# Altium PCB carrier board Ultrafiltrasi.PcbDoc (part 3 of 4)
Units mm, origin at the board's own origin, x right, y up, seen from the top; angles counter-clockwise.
Board outline 196.34 x 220.85 mm, 2 copper layers (Top Layer, Bottom Layer); 114 components, 209 nets, 667 pads, 70 vias.
Unrouted connection lines stored in the file: 5.
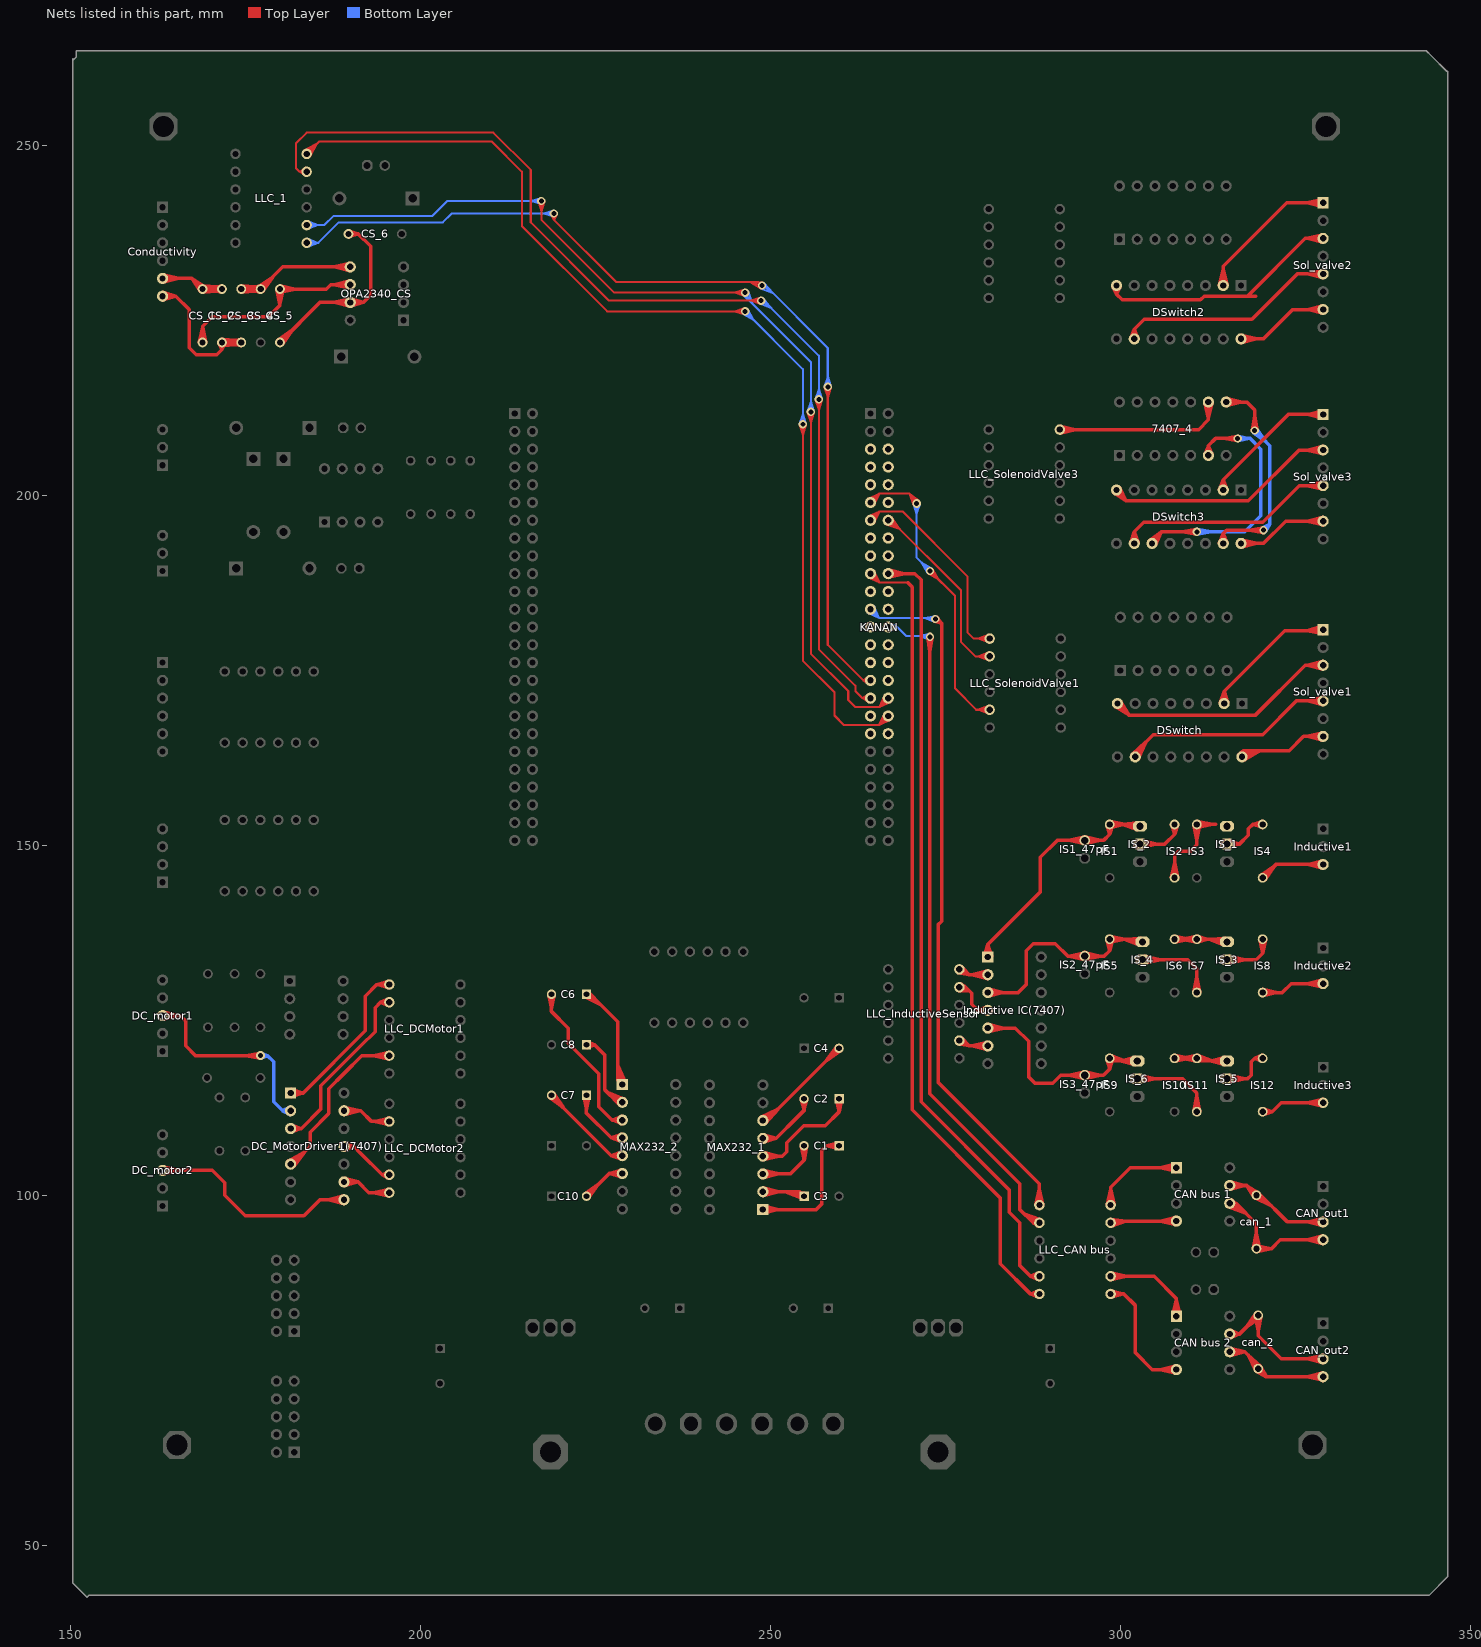
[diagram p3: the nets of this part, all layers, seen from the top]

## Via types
v1: diameter 1.2, hole 0.711, Top Layer to Bottom Layer, 26 vias
v2: diameter 1.27, hole 0.711, Top Layer to Bottom Layer, 24 vias
v3: diameter 1.2, hole 0.7, Top Layer to Bottom Layer, 19 vias
v4: diameter 1.5, hole 0.8, Top Layer to Bottom Layer, 1 vias

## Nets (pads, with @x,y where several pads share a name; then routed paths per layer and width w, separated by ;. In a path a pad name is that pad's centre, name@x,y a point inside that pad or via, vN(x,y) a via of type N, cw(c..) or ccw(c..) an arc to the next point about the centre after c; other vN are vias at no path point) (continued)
Net7407_4_6: 7407_4.6 DSwitch3.11 | length 64.6
  Top Layer w0.5: DSwitch3.11@304.124,193.562 305.816,194.818 ; DSwitch3.11@304.979,192.884 305.816,194.818 ; v3@310.867,194.469 308.796,194.818 v3@310.867,195.167 ; v3@311.162,195.072 311.15,195.072 v3(310.896,194.818) 305.816,194.818 ; 7407_4.6@312.008,205.848 312.547,207.137 ; 7407_4.6@312.547,205.74 312.547,207.137 ; 7407_4.6@313.086,205.848 312.547,207.137 ; v1@316.709,207.804 314.638,208.153 ; v1@316.709,208.502 314.638,208.153 ; 305.816,194.818 DSwitch3.11@304.507,193.167 304.507,193.509 305.816,194.818 ; 312.547,207.137 313.563,208.153 v1(316.738,208.153) 314.638,208.153
  Bottom Layer w0.5: v3(310.896,194.818) 317.754,194.818 320.04,197.104 320.04,206.629 318.516,208.153 ; v3@310.925,194.469 312.996,194.818 v3@310.925,195.167 ; v1(316.738,208.153) 318.516,208.153 ; v1@316.772,207.805 318.516,208.153 ; v1@316.772,208.501 318.516,208.153
Net7407_4_8: 7407_4.8 DSwitch3.15 | length 55.5
  Top Layer w0.5: DSwitch3.15@314.127,193.272 314.667,194.603 ; DSwitch3.15@314.667,193.167 314.667,194.603 ; 7407_4.8@315.087,213.36 318.008,213.36 319.151,212.217 v3(319.151,209.296) ; 7407_4.8@315.153,212.814 317.387,213.36 7407_4.8@315.153,213.906 ; DSwitch3.15@315.207,193.272 314.667,194.603 ; v3@318.802,209.325 319.151,211.396 v3@319.5,209.325 ; v3@320.392,194.723 318.321,195.072 ; v3@320.392,195.421 318.321,195.072 ; 314.667,194.603 315.136,195.072 v3(320.421,195.072) 318.321,195.072
  Bottom Layer w0.5: v3@318.923,209.031 320.812,207.635 v3@319.416,209.524 ; v3(319.151,209.296) 321.31,207.137 321.31,195.961 ; v3@320.21,195.352 321.31,195.961 ; v3(320.421,195.072) 321.31,195.961 ; v3@320.701,194.861 321.31,195.961
Net7407_4_9: 7407_4.9 LLC_SolenoidValve3.P$12 | length 33.4
  Top Layer w0.5: LLC_SolenoidValve3.P$12@291.338,209.423 311.15,209.423 312.547,210.82 7407_4.9@312.547,213.36 ; LLC_SolenoidValve3.P$12@291.394,208.926 293.588,209.423 LLC_SolenoidValve3.P$12@291.394,209.92 ; 7407_4.9@312.001,213.294 312.547,211.06 7407_4.9@313.093,213.294
NetC1_1: C1.1 MAX232_1.1 | length 27.3
  Top Layer w0.5: MAX232_1.1@248.92,98.044 256.54,98.044 257.302,98.806 257.302,106.426 258.032,107.156 ; MAX232_1.1@248.986,97.498 251.22,98.044 MAX232_1.1@248.986,98.59 ; C1.1@259.751,106.734 258.032,107.156 ; C1.1@259.751,107.578 258.032,107.156 ; C1.1@259.802,107.156 258.032,107.156
NetC1_2: C1.2 MAX232_1.3 | length 19.6
  Top Layer w0.5: MAX232_1.3@248.92,103.124 252.857,103.124 254.802,105.069 ; MAX232_1.3@248.986,102.578 251.22,103.124 MAX232_1.3@248.986,103.67 ; C1.2@254.379,107.113 254.802,105.069 ; C1.2@255.225,107.113 254.802,105.069 ; 254.802,105.069 C1.2@254.802,107.156 254.802,105.069
NetC2_1: C2.1 MAX232_1.4 | length 26.6
  Top Layer w0.5: MAX232_1.4@248.92,105.664 251.714,105.664 252.349,106.299 252.349,107.569 254.762,109.982 257.81,109.982 259.802,111.974 ; MAX232_1.4@248.986,105.118 251.22,105.664 MAX232_1.4@248.986,106.21 ; C2.1@259.38,113.807 259.802,111.974 ; C2.1@259.802,113.855 259.802,111.974 ; C2.1@259.802,114.088 259.802,111.974 ; C2.1@260.224,113.807 259.802,111.974
NetC2_2: C2.2 MAX232_1.5 | length 18
  Top Layer w0.5: MAX232_1.5@248.92,108.204 250.825,108.204 ; MAX232_1.5@248.999,107.66 250.825,108.204 ; MAX232_1.5@248.999,108.748 250.825,108.204 ; C2.2@254.38,113.802 254.802,112.181 ; C2.2@255.224,113.802 254.802,112.181 ; 250.825,108.204 253.873,111.252 254.802,112.181 ; 254.802,112.181 C2.2@254.802,113.855 254.802,112.181
NetC3_1: C3.1 MAX232_1.2 | length 19.1
  Top Layer w0.5: MAX232_1.2@248.92,100.584 254.167,100.584 C3.1@254.802,99.949 252.103,100.584 ; MAX232_1.2@248.986,100.038 251.22,100.584 MAX232_1.2@248.986,101.13 ; C3.1@254.673,99.544 252.103,100.584 ; C3.1@254.867,100.369 252.103,100.584
NetC4_2: C4.2 MAX232_1.6 | length 30.6
  Top Layer w0.5: MAX232_1.6@248.633,111.213 251.066,112.382 ; MAX232_1.6@249.297,110.343 251.066,112.382 ; C4.2@259.481,121.341 258.04,119.356 ; C4.2@259.774,121.09 249.428,110.744 MAX232_1.6@248.92,110.744 251.066,112.382 ; C4.2@259.802,121.063 258.04,119.356 ; C4.2@260.07,120.733 258.04,119.356
NetC6_1: C6.1 MAX232_2.1 | length 31.3
  Top Layer w0.5: C6.1@223.513,128.415 225.771,127.289 ; C6.1@224.013,129.099 225.771,127.289 ; MAX232_2.1@228.309,115.821 228.219,118.628 ; MAX232_2.1@229.375,116.068 228.219,118.628 ; 225.771,127.289 C6.1@223.734,128.778 224.282,128.778 228.219,124.841 228.219,116.527 MAX232_2.1@228.854,115.892 228.219,118.628
NetC6_2: C6.2 MAX232_2.3 | length 31.8
  Top Layer w0.5: C6.2@218.311,128.736 218.734,126.603 C6.2@219.157,128.736 ; C6.2@218.734,128.778 218.734,126.325 221.107,123.952 221.107,121.793 225.464,117.436 225.464,112.737 227.389,110.812 ; MAX232_2.3@228.751,110.272 227.389,110.812 ; MAX232_2.3@228.751,111.352 227.389,110.812 ; 227.389,110.812 MAX232_2.3@228.854,110.812 227.389,110.812
NetC7_1: C7.1 MAX232_2.4 | length 20.4
  Top Layer w0.5: C7.1@223.311,114.322 223.734,112.189 ; C7.1@224.157,114.322 223.734,112.189 ; MAX232_2.4@228.759,107.73 227.262,108.272 ; MAX232_2.4@228.759,108.814 227.262,108.272 ; 223.734,112.189 C7.1@223.734,114.364 223.734,111.8 227.262,108.272 ; 227.262,108.272 MAX232_2.4@228.854,108.272 227.262,108.272
NetC7_2: C7.2 MAX232_2.5 | length 24.3
  Top Layer w0.5: C7.2@218.451,114.046 220.415,112.579 ; C7.2@218.63,114.364 227.262,105.732 ; C7.2@218.734,114.364 220.415,112.579 ; C7.2@219.067,114.627 220.415,112.579 ; MAX232_2.5@228.759,105.19 227.262,105.732 ; MAX232_2.5@228.759,106.274 227.262,105.732 ; MAX232_2.5@228.854,105.732 227.262,105.732
NetC8_1: C8.1 MAX232_2.2 | length 21.6
  Top Layer w0.5: C8.1@223.734,121.571 224.885,121.571 ; C8.1@223.812,121.153 224.885,121.571 ; C8.1@223.812,121.988 224.885,121.571 ; MAX232_2.2@228.5,112.931 226.676,114.827 ; MAX232_2.2@229.113,113.837 226.676,114.827 ; 224.885,121.571 226.314,120.142 226.314,115.189 228.151,113.352 MAX232_2.2@228.854,113.352 226.676,114.827
NetC10_2: C10.2 MAX232_2.6 | length 15.1
  Top Layer w0.5: C10.2@223.461,100.274 225.47,101.685 C10.2@224.059,99.676 ; C10.2@223.734,99.949 226.977,103.192 ; MAX232_2.6@228.773,102.648 226.977,103.192 ; MAX232_2.6@228.773,103.736 226.977,103.192 ; MAX232_2.6@228.854,103.192 226.977,103.192
"NetCAN bus 1_1": "CAN bus 1.1" "LLC_CAN bus.P$12" | length 22.2
  Top Layer w0.5: 298.08,98.735 298.577,100.929 299.074,98.735 ; 298.577,98.679 298.577,101.219 301.371,104.013 307.975,104.013 ; 307.909,103.467 305.675,104.013 307.909,104.559
"NetCAN bus 1_4": "CAN bus 1.4" "LLC_CAN bus.P$11" | length 23.4
  Top Layer w0.5: 298.576,96.639 300.879,96.393 ; 298.685,95.651 300.879,96.393 ; 307.909,95.847 305.675,96.393 ; 307.909,96.939 305.675,96.393 ; 300.879,96.393 298.577,96.139 298.831,96.393 307.975,96.393 305.675,96.393
"NetCAN bus 2_1": "CAN bus 2.1" "LLC_CAN bus.P$8" | length 22.4
  Top Layer w0.5: 298.577,88.519 304.8,88.519 307.975,85.344 307.975,82.804 ; 298.633,88.022 300.827,88.519 298.633,89.016 ; 307.429,82.87 307.975,85.104 308.521,82.87
"NetCAN bus 2_4": "CAN bus 2.4" "LLC_CAN bus.P$7" | length 26.2
  Top Layer w0.5: 298.577,85.979 300.482,85.979 ; 298.643,85.483 300.482,85.979 ; 298.643,86.475 300.482,85.979 ; 307.909,74.638 305.675,75.184 307.909,75.73 ; 307.975,75.184 304.546,75.184 302.133,77.597 302.133,84.328 300.482,85.979
Netcan_1_1: "CAN bus 1.6" can_1.1 CAN_out1.4 | length 44.5
  Top Layer w0.5: 315.357,98.437 317.889,97.528 ; 315.929,99.37 317.889,97.528 ; can_1.1@318.957,92.502 319.405,94.656 can_1.1@319.853,92.502 ; can_1.1@319.452,92.008 321.564,92.456 ; can_1.1@319.452,92.904 321.564,92.456 ; CAN_out1.4@328.864,93.18 326.63,93.726 CAN_out1.4@328.864,94.272 ; CAN_out1.4@328.93,93.726 322.834,93.726 321.564,92.456 ; 315.595,98.933 316.484,98.933 ; 315.595,98.933 317.889,97.528 ; 315.595,98.933 316.484,98.933 ; 316.484,98.933 315.765,98.41 316.484,98.933 ; 316.484,98.933 315.765,99.456 316.484,98.933 ; 316.484,98.933 319.405,96.012 can_1.1@319.405,92.456 321.564,92.456
Netcan_1_2: "CAN bus 1.7" can_1.2 CAN_out1.3 | length 36.4
  Top Layer w0.5: 315.595,101.473 318.008,101.473 ; 315.661,100.927 317.895,101.473 315.661,102.019 ; can_1.2@319.053,99.796 318.008,101.473 ; can_1.2@319.18,99.686 321.527,98.589 ; can_1.2@319.685,100.428 318.008,101.473 ; can_1.2@319.694,100.421 321.527,98.589 ; CAN_out1.3@328.864,95.72 326.63,96.266 CAN_out1.3@328.864,96.812 ; CAN_out1.3@328.93,96.266 323.85,96.266 320.04,100.076 can_1.2@319.405,100.076 ; 318.008,101.473 can_1.2@319.405,100.076 ; can_1.2@319.405,100.076 321.527,98.589
Netcan_2_1: "CAN bus 2.6" can_2.1 CAN_out2.4 | length 34.7
  Top Layer w0.5: 315.595,77.724 317.754,77.724 ; 315.665,77.178 317.754,77.724 ; 315.665,78.27 317.754,77.724 ; can_2.1@319.275,75.076 318.185,77.293 ; can_2.1@319.388,74.952 320.802,74.168 ; can_2.1@319.994,75.611 318.185,77.293 ; can_2.1@320.018,75.582 320.802,74.168 ; CAN_out2.4@328.864,73.622 326.63,74.168 CAN_out2.4@328.864,74.714 ; CAN_out2.4@328.93,74.168 320.802,74.168 ; 317.754,77.724 319.659,75.819 can_2.1@319.659,75.311 ; 318.185,77.293 can_2.1@319.659,75.311 ; can_2.1@319.659,75.311 320.802,74.168
Netcan_2_2: "CAN bus 2.7" can_2.2 CAN_out2.3 | length 35.5
  Top Layer w0.5: 315.595,80.264 316.992,80.264 ; 315.703,79.725 316.992,80.264 ; 315.703,80.803 316.992,80.264 ; can_2.2@319.211,82.885 319.659,80.731 can_2.2@320.107,82.885 ; can_2.2@319.313,83.219 317.898,81.17 can_2.2@319.947,82.585 ; CAN_out2.3@328.864,76.162 326.63,76.708 CAN_out2.3@328.864,77.254 ; CAN_out2.3@328.93,76.708 322.961,76.708 319.659,80.01 can_2.2@319.659,82.931 316.992,80.264
NetConductivity_5: Conductivity.5 CS_1.1 CS_2.2 | length 40.2
  Top Layer w0.5: Conductivity.5@163.195,231.013 167.386,231.013 ; Conductivity.5@163.261,230.467 165.495,231.013 Conductivity.5@163.261,231.559 ; CS_1.1@168.56,229.206 167.386,231.013 ; CS_1.1@168.886,229.04 CS_2.2@171.117,229.147 ; CS_1.1@168.886,229.938 CS_2.2@171.117,229.831 ; CS_1.1@168.956,229.041 171.11,229.489 CS_1.1@168.956,229.937 ; CS_1.1@169.023,229.054 CS_2.2@171.117,229.831 ; CS_1.1@169.023,229.924 CS_2.2@171.117,229.147 ; CS_1.1@169.193,229.839 167.386,231.013 ; CS_2.2@171.626,229.041 169.472,229.489 CS_2.2@171.626,229.937 ; CS_2.2@171.672,229.489 CS_1.1@168.91,229.489 ; 167.386,231.013 CS_1.1@168.91,229.489 ; CS_1.1@168.91,229.489 CS_2.2@171.117,229.831 ; CS_1.1@168.91,229.489 CS_2.2@171.117,229.147
NetConductivity_6: Conductivity.6 CS_2.1 CS_3.1 | length 47.4
  Top Layer w0.5: Conductivity.6@163.195,228.473 165.1,228.473 ; Conductivity.6@163.274,227.929 165.1,228.473 ; Conductivity.6@163.274,229.017 165.1,228.473 ; CS_2.1@171.233,221.772 171.672,220.821 ; CS_2.1@171.649,221.42 CS_3.1@173.879,221.527 ; CS_2.1@171.649,222.318 CS_3.1@173.879,222.211 ; CS_2.1@171.718,221.421 173.872,221.869 CS_2.1@171.718,222.317 ; CS_2.1@171.786,221.434 CS_3.1@173.879,222.211 ; CS_2.1@171.786,222.304 CS_3.1@173.879,221.527 ; CS_2.1@172.112,221.772 171.672,220.821 ; CS_3.1@174.388,221.421 172.235,221.869 CS_3.1@174.388,222.317 ; CS_3.1@174.434,221.869 CS_2.1@171.672,221.869 ; 165.1,228.473 167.005,226.568 167.005,221.107 168.021,220.091 170.942,220.091 171.672,220.821 ; 171.672,220.821 CS_2.1@171.672,221.869 ; CS_2.1@171.672,221.869 CS_3.1@173.879,221.527 ; CS_2.1@171.672,221.869 CS_3.1@173.879,222.211
NetCS_1_2: CS_1.2 CS_5.1 OPA2340_CS.6 | length 47.2
  Top Layer w0.5: CS_1.2@168.462,221.915 168.91,224.069 CS_1.2@169.358,221.915 ; CS_1.2@168.91,221.869 168.91,224.155 170.307,225.552 178.308,225.552 179.959,227.203 CS_5.1@179.959,229.489 ; CS_5.1@179.511,229.443 179.959,227.289 ; CS_5.1@180.005,229.041 182.159,229.489 CS_5.1@180.005,229.937 ; CS_5.1@180.407,229.443 179.959,227.289 ; OPA2340_CS.6@189.926,229.578 187.692,230.124 OPA2340_CS.6@189.926,230.67 ; OPA2340_CS.6@189.992,230.124 187.198,230.124 186.563,229.489 CS_5.1@179.959,229.489 ; 179.959,227.289 CS_5.1@179.959,229.489
NetCS_3_2: CS_3.2 CS_4.2 OPA2340_CS.5 | length 48.7
  Top Layer w0.5: CS_3.2@174.411,229.04 CS_4.2@176.641,229.147 ; CS_3.2@174.411,229.938 CS_4.2@176.641,229.831 ; CS_3.2@174.481,229.041 176.634,229.489 CS_3.2@174.481,229.937 ; CS_3.2@174.548,229.054 CS_4.2@176.641,229.831 ; CS_3.2@174.548,229.924 CS_4.2@176.641,229.147 ; CS_4.2@176.909,229.835 178.957,231.25 CS_4.2@177.542,229.201 ; CS_4.2@177.151,229.041 174.997,229.489 CS_4.2@177.151,229.937 ; OPA2340_CS.5@189.926,232.118 187.692,232.664 OPA2340_CS.5@189.926,233.21 ; OPA2340_CS.5@189.992,232.664 180.372,232.664 CS_4.2@177.197,229.489 CS_3.2@174.434,229.489 ; CS_3.2@174.434,229.489 CS_4.2@176.641,229.831 ; CS_3.2@174.434,229.489 CS_4.2@176.641,229.147
NetCS_5_2: CS_5.2 CS_6.1 OPA2340_CS.7 | length 42.8
  Top Layer w0.5: CS_5.2@179.671,222.215 181.72,223.63 CS_5.2@180.305,221.581 ; CS_5.2@179.959,221.869 185.674,227.584 OPA2340_CS.7@189.992,227.584 191.897,227.584 ; CS_6.1@189.738,237.363 191.135,237.363 ; CS_6.1@189.81,236.919 191.135,237.363 ; CS_6.1@189.81,237.807 191.135,237.363 ; OPA2340_CS.7@189.926,227.038 187.692,227.584 OPA2340_CS.7@189.926,228.13 ; OPA2340_CS.7@190.071,227.04 191.897,227.584 ; OPA2340_CS.7@190.071,228.128 191.897,227.584 ; 191.135,237.363 192.913,235.585 192.913,228.6 191.897,227.584
NetDC_motor1_3: DC_motor1.3 DC_MotorDriver1(7407).2 | length 44.7
  Top Layer w0.5: DC_motor1.3@163.195,125.73 165.735,125.73 166.497,124.968 166.497,121.412 167.894,120.015 v2(177.165,120.015) 175.03,120.015 ; DC_motor1.3@163.261,125.184 165.495,125.73 DC_motor1.3@163.261,126.276 ; v2@177.13,119.632 175.03,120.015 ; v2@177.13,120.398 175.03,120.015
  Bottom Layer w0.5: v2(177.165,120.015) 178.181,120.015 ; v2@177.238,119.637 178.181,120.015 ; v2@177.238,120.393 178.181,120.015 ; 181.351,111.607 180.34,112.141 ; 181.351,112.675 180.34,112.141 ; 181.483,112.141 180.34,112.141 ; 178.181,120.015 179.07,119.126 179.07,113.411 180.34,112.141
NetDC_motor2_3: DC_motor2.3 DC_MotorDriver1(7407).8 | length 39.8
  Top Layer w0.5: DC_motor2.3@163.195,103.632 170.307,103.632 172.085,101.854 172.085,100.076 175.006,97.155 183.388,97.155 185.674,99.441 189.103,99.441 ; DC_motor2.3@163.261,103.086 165.495,103.632 DC_motor2.3@163.261,104.178 ; 189.037,98.895 186.803,99.441 189.037,99.987
NetDC_MotorDriver1(7407)_1: DC_MotorDriver1(7407).1 LLC_DCMotor1.P$7 | length 32.3
  Top Layer w0.5: 181.483,114.681 183.261,114.681 ; 181.568,114.138 183.261,114.681 ; 181.568,115.224 183.261,114.681 ; LLC_DCMotor1.P$7@195.51,129.68 193.802,130.175 ; LLC_DCMotor1.P$7@195.51,130.67 193.802,130.175 ; 183.261,114.681 192.151,123.571 192.151,128.524 193.802,130.175 ; 193.802,130.175 LLC_DCMotor1.P$7@195.58,130.175 193.802,130.175
NetDC_MotorDriver1(7407)_3: DC_MotorDriver1(7407).3 LLC_DCMotor1.P$8 | length 32.4
  Top Layer w0.5: 181.483,109.601 183.007,109.601 ; 181.582,109.06 183.007,109.601 ; 181.582,110.142 183.007,109.601 ; LLC_DCMotor1.P$8@195.482,127.145 194.31,127.635 ; LLC_DCMotor1.P$8@195.482,128.125 194.31,127.635 ; 183.007,109.601 185.801,112.395 185.801,115.697 191.516,121.412 193.548,123.444 193.548,126.873 194.31,127.635 ; 194.31,127.635 LLC_DCMotor1.P$8@195.58,127.635 194.31,127.635
NetDC_MotorDriver1(7407)_5: DC_MotorDriver1(7407).5 LLC_DCMotor1.P$11 | length 36.1
  Top Layer w0.5: 181.168,104.972 183.441,106.225 ; 181.886,104.147 183.441,106.225 ; LLC_DCMotor1.P$11@195.524,119.518 193.33,120.015 LLC_DCMotor1.P$11@195.524,120.512 ; LLC_DCMotor1.P$11@195.58,120.015 191.643,120.015 189.103,117.475 186.944,115.316 186.944,111.76 184.277,109.093 184.277,107.061 181.737,104.521 181.483,104.521 183.441,106.225
NetDC_MotorDriver1(7407)_9: DC_MotorDriver1(7407).9 LLC_DCMotor2.P$12 | length 15.7
  Top Layer w0.5: 189.103,101.981 191.135,101.981 ; 189.177,101.436 191.135,101.981 ; 189.177,102.526 191.135,101.981 ; LLC_DCMotor2.P$12@195.524,99.96 193.33,100.457 LLC_DCMotor2.P$12@195.524,100.954 ; LLC_DCMotor2.P$12@195.58,100.457 192.659,100.457 191.135,101.981
NetDC_MotorDriver1(7407)_11: DC_MotorDriver1(7407).11 LLC_DCMotor2.P$11 | length 13
  Top Layer w0.5: 189.103,107.061 190.5,107.061 ; 189.211,106.522 190.5,107.061 ; 189.211,107.6 190.5,107.061 ; LLC_DCMotor2.P$11@195.457,102.512 194.564,102.997 ; LLC_DCMotor2.P$11@195.457,103.482 194.564,102.997 ; LLC_DCMotor2.P$11@195.58,102.997 194.564,102.997 ; 190.5,107.061 191.516,106.045 194.564,102.997
NetDC_MotorDriver1(7407)_13: DC_MotorDriver1(7407).13 LLC_DCMotor2.P$8 | length 16.2
  Top Layer w0.5: 189.103,112.141 191.516,112.141 193.04,110.617 LLC_DCMotor2.P$8@195.58,110.617 ; 189.169,111.595 191.403,112.141 189.169,112.687 ; LLC_DCMotor2.P$8@195.524,110.12 193.33,110.617 LLC_DCMotor2.P$8@195.524,111.114
NetDSwitch2_2: DSwitch2.2 Sol_valve2.1 | length 32.1
  Top Layer w0.5: DSwitch2.2@314.121,230.063 314.667,232.297 DSwitch2.2@315.213,230.063 ; DSwitch2.2@314.667,229.997 314.667,232.752 323.723,241.808 Sol_valve2.1@328.803,241.808 ; Sol_valve2.1@328.864,241.262 326.63,241.808 ; Sol_valve2.1@328.864,242.354 326.63,241.808 ; Sol_valve2.1@328.93,241.808 326.63,241.808
NetDSwitch2_8: DSwitch2.8 Sol_valve2.3 | length 45.1
  Top Layer w0.5: DSwitch2.8@298.891,229.874 299.427,228.766 ; DSwitch2.8@299.427,229.997 299.427,228.766 ; DSwitch2.8@299.963,229.874 299.427,228.766 ; 318.135,228.473 326.39,236.728 Sol_valve2.3@328.803,236.728 ; 319.278,228.473 311.942,228.473 311.419,227.95 300.243,227.95 299.427,228.766 ; Sol_valve2.3@328.864,236.182 326.63,236.728 ; Sol_valve2.3@328.864,237.274 326.63,236.728 ; Sol_valve2.3@328.93,236.728 326.63,236.728
NetDSwitch2_10: DSwitch2.10 Sol_valve2.5 | length 41
  Top Layer w0.5: DSwitch2.10@301.428,222.488 301.967,223.735 ; DSwitch2.10@301.967,222.377 301.967,223.735 ; DSwitch2.10@302.506,222.488 301.967,223.735 ; Sol_valve2.5@328.676,231.648 325.247,231.648 318.77,225.171 303.403,225.171 301.967,223.735 ; Sol_valve2.5@328.864,231.102 326.63,231.648 ; Sol_valve2.5@328.864,232.194 326.63,231.648 ; Sol_valve2.5@328.93,231.648 326.63,231.648
NetDSwitch2_16: DSwitch2.16 Sol_valve2.7 | length 22.7
  Top Layer w0.5: DSwitch2.16@317.207,222.377 320.421,222.377 324.612,226.568 Sol_valve2.7@328.93,226.568 ; DSwitch2.16@317.273,221.831 319.507,222.377 DSwitch2.16@317.273,222.923 ; Sol_valve2.7@328.864,226.022 326.63,226.568 Sol_valve2.7@328.864,227.114
NetDSwitch3_2: DSwitch3.2 Sol_valve3.1 | length 29.2
  Top Layer w0.5: DSwitch3.2@314.127,200.889 314.667,202.272 ; DSwitch3.2@314.667,200.787 314.667,202.272 ; DSwitch3.2@315.208,200.889 314.667,202.272 ; 323.977,211.582 314.667,202.272 ; 324.104,211.582 Sol_valve3.1@328.803,211.582 ; Sol_valve3.1@328.864,211.036 326.63,211.582 ; Sol_valve3.1@328.864,212.128 326.63,211.582 ; Sol_valve3.1@328.93,211.582 326.63,211.582
NetDSwitch3_8: DSwitch3.8 Sol_valve3.3 | length 45.9
  Top Layer w0.5: DSwitch3.8@299.063,200.375 300.736,199.263 ; DSwitch3.8@299.889,201.085 300.736,199.263 ; Sol_valve3.3@328.676,206.502 325.501,206.502 318.262,199.263 300.736,199.263 ; Sol_valve3.3@328.864,205.956 326.63,206.502 ; Sol_valve3.3@328.864,207.048 326.63,206.502 ; Sol_valve3.3@328.93,206.502 326.63,206.502 ; 300.736,199.263 DSwitch3.8@299.427,200.787 299.427,200.572 300.736,199.263
NetDSwitch3_10: DSwitch3.10 Sol_valve3.5 | length 41.4
  Top Layer w0.5: DSwitch3.10@301.424,193.256 301.967,194.857 ; DSwitch3.10@301.967,193.167 301.967,194.857 ; DSwitch3.10@302.51,193.256 301.967,194.857 ; Sol_valve3.5@328.676,201.422 325.501,201.422 320.294,196.215 303.325,196.215 301.967,194.857 ; Sol_valve3.5@328.864,200.876 326.63,201.422 ; Sol_valve3.5@328.864,201.968 326.63,201.422 ; Sol_valve3.5@328.93,201.422 326.63,201.422
NetDSwitch3_16: DSwitch3.16 Sol_valve3.7 | length 24.3
  Top Layer w0.5: DSwitch3.16@317.207,193.167 320.421,193.167 323.596,196.342 Sol_valve3.7@328.676,196.342 ; DSwitch3.16@317.273,192.621 319.507,193.167 DSwitch3.16@317.273,193.713 ; Sol_valve3.7@328.864,195.796 326.63,196.342 ; Sol_valve3.7@328.864,196.888 326.63,196.342 ; Sol_valve3.7@328.93,196.342 326.63,196.342
NetDSwitch_2: DSwitch.2 Sol_valve1.1 | length 29.9
  Top Layer w0.5: DSwitch.2@314.251,170.394 314.794,172.046 ; DSwitch.2@314.794,170.307 314.794,172.046 ; DSwitch.2@315.337,170.394 314.794,172.046 ; Sol_valve1.1@328.835,181.39 326.623,180.721 ; Sol_valve1.1@328.895,180.299 326.623,180.721 ; Sol_valve1.1@328.93,180.721 323.469,180.721 314.794,172.046 ; Sol_valve1.1@328.93,180.848 326.623,180.721
NetDSwitch_8: DSwitch.8 Sol_valve1.3 | length 42.3
  Top Layer w0.5: DSwitch.8@299.214,169.875 301.205,168.656 ; DSwitch.8@299.554,170.307 301.205,168.656 ; DSwitch.8@299.986,170.647 301.205,168.656 ; Sol_valve1.3@328.864,175.222 326.63,175.768 Sol_valve1.3@328.864,176.314 ; Sol_valve1.3@328.93,175.768 326.39,175.768 319.278,168.656 301.205,168.656
NetDSwitch_10: DSwitch.10 Sol_valve1.5 | length 50.7
  Top Layer w0.5: DSwitch.10@301.684,163.053 303.615,164.804 ; DSwitch.10@302.572,162.415 303.615,164.804 ; 324.993,170.561 320.294,165.862 304.673,165.862 302.387,163.576 ; 325.12,170.688 Sol_valve1.5@328.93,170.688 326.63,170.688 ; Sol_valve1.5@328.864,170.142 326.63,170.688 ; Sol_valve1.5@328.864,171.234 326.63,170.688 ; DSwitch.10@302.094,162.687 302.387,163.576 ; DSwitch.10@302.094,162.687 303.615,164.804 ; DSwitch.10@302.094,162.687 302.387,163.576 ; DSwitch.10@302.094,162.687 302.387,162.98 302.387,163.576 ; 302.387,163.576 302.644,162.676 302.387,163.576 ; 302.387,163.576 301.645,163.005 302.387,163.576
NetDSwitch_16: DSwitch.16 Sol_valve1.7 | length 32.6
  Top Layer w0.5: DSwitch.16@317.21,163.223 319.954,163.576 ; DSwitch.16@317.562,162.186 319.954,163.576 ; Sol_valve1.7@328.781,165.079 327.914,165.608 ; Sol_valve1.7@328.781,166.137 327.914,165.608 ; Sol_valve1.7@328.864,165.062 326.63,165.608 Sol_valve1.7@328.864,166.154 ; DSwitch.16@317.334,162.687 317.5,163.576 ; DSwitch.16@317.334,162.687 319.954,163.576 ; DSwitch.16@317.334,162.687 317.5,163.576 ; DSwitch.16@317.334,162.687 317.334,163.41 317.5,163.576 ; 317.5,163.576 317.88,162.755 317.5,163.576 ; 317.5,163.576 316.85,162.948 317.5,163.576 ; 317.5,163.576 324.104,163.576 326.136,165.608 327.914,165.608
NetInductive1_3: Inductive1.3 IS4.2 | length 19
  Top Layer w0.5: IS4.2@320.006,145.761 322.055,147.176 IS4.2@320.64,145.127 ; IS4.2@320.294,145.415 322.199,147.32 Inductive1.3@328.93,147.32 ; Inductive1.3@328.864,146.774 326.63,147.32 Inductive1.3@328.864,147.866
NetInductive2_3: Inductive2.3 IS8.2 | length 18.2
  Top Layer w0.5: IS8.2@320.294,129.032 323.088,129.032 324.358,130.302 Inductive2.3@328.93,130.302 ; IS8.2@320.34,128.584 322.494,129.032 IS8.2@320.34,129.48 ; Inductive2.3@328.864,129.756 326.63,130.302 Inductive2.3@328.864,130.848
NetInductive3_3: Inductive3.3 IS12.2 | length 16.5
  Top Layer w0.5: IS12.2@320.294,112.014 321.691,112.014 ; IS12.2@320.366,111.57 321.691,112.014 ; IS12.2@320.366,112.458 321.691,112.014 ; Inductive3.3@328.874,112.787 326.68,113.284 Inductive3.3@328.874,113.781 ; Inductive3.3@328.93,113.284 322.961,113.284 321.691,112.014
"NetInductive IC(7407)_1": "Inductive IC(7407).1" IS1.2 IS1_47pF.2 IS_2.1 | length 61.1
  Top Layer w0.5: 280.508,134.197 281.051,135.89 ; 281.051,134.112 281.051,135.89 ; 281.594,134.197 281.051,135.89 ; IS1_47pF.2@294.836,150.24 292.632,150.749 IS1_47pF.2@294.836,151.258 ; IS1_47pF.2@294.952,150.24 297.156,150.749 IS1_47pF.2@294.952,151.258 ; IS1.2@298.006,152.963 298.45,151.638 ; IS1.2@298.496,152.587 300.65,153.035 IS1.2@298.496,153.483 ; IS1.2@298.894,152.963 298.45,151.638 ; IS_2.1@302.401,152.282 300.228,153.035 ; IS_2.1@302.514,152.781 300.228,153.035 ; IS_2.1@302.514,153.293 300.228,153.035 ; IS_2.1@302.768,152.781 302.514,153.035 IS1.2@298.45,153.035 298.45,151.638 ; 281.051,135.89 288.544,143.383 288.544,148.336 290.957,150.749 IS1_47pF.2@294.894,150.749 297.561,150.749 298.45,151.638
"NetInductive IC(7407)_2": "Inductive IC(7407).2" LLC_InductiveSensor.P$12 | length 13.8
  Top Layer w0.5: LLC_InductiveSensor.P$12@276.82,131.863 278.384,131.572 ; LLC_InductiveSensor.P$12@276.987,132.334 278.384,131.572 ; LLC_InductiveSensor.P$12@276.987,132.461 277.495,132.461 278.384,131.572 ; LLC_InductiveSensor.P$12@277.292,132.73 278.384,131.572 ; 280.985,131.026 278.751,131.572 280.985,132.118 ; 281.051,131.572 278.384,131.572
"NetInductive IC(7407)_3": "Inductive IC(7407).3" IS2_47pF.2 IS5.2 IS_4.1 | length 61.4
  Top Layer w0.5: 281.051,129.032 285.369,129.032 286.512,130.175 286.512,135.001 287.528,136.017 290.703,136.017 292.481,134.239 IS2_47pF.2@294.894,134.239 ; 281.117,128.486 283.351,129.032 281.117,129.578 ; IS2_47pF.2@294.836,133.73 292.632,134.239 ; IS2_47pF.2@294.836,134.748 292.632,134.239 ; IS2_47pF.2@294.952,133.73 297.156,134.239 IS2_47pF.2@294.952,134.748 ; IS5.2@298.004,136.591 298.45,135.001 ; IS5.2@298.496,136.204 300.65,136.652 IS5.2@298.496,137.1 ; IS5.2@298.896,136.591 298.45,135.001 ; IS_4.1@302.758,135.778 300.566,136.652 ; IS_4.1@302.895,136.271 300.566,136.652 ; IS_4.1@302.922,136.782 300.566,136.652 ; IS_4.1@303.149,136.271 302.768,136.652 IS5.2@298.45,136.652 298.45,135.001 ; 292.632,134.239 IS2_47pF.2@294.894,134.239 ; IS2_47pF.2@294.894,134.239 297.688,134.239 298.45,135.001
"NetInductive IC(7407)_4": "Inductive IC(7407).4" LLC_InductiveSensor.P$11 | length 18.3
  Top Layer w0.5: LLC_InductiveSensor.P$11@276.898,129.302 278.384,129.286 ; LLC_InductiveSensor.P$11@276.987,129.921 277.749,129.921 ; LLC_InductiveSensor.P$11@277.234,130.228 278.384,129.286 ; 280.943,125.953 279.654,126.492 ; 280.943,127.031 279.654,126.492 ; 281.051,126.492 279.654,126.492 ; LLC_InductiveSensor.P$11@276.987,129.794 277.749,129.921 ; LLC_InductiveSensor.P$11@276.987,129.794 278.384,129.286 ; LLC_InductiveSensor.P$11@276.987,129.794 277.749,129.921 ; 277.749,129.921 277.224,129.354 277.749,129.921 ; 277.749,129.921 277.069,130.287 277.749,129.921 ; 277.749,129.921 278.384,129.286 ; 278.384,129.286 278.765,128.905 278.765,127.381 279.654,126.492
"NetInductive IC(7407)_5": "Inductive IC(7407).5" IS3_47pF.2 IS9.2 IS_6.1 | length 62.9
  Top Layer w0.5: 281.051,123.952 284.988,123.952 286.893,122.047 286.893,116.967 287.782,116.078 290.322,116.078 291.465,117.221 IS3_47pF.2@294.894,117.221 ; 281.117,123.406 283.351,123.952 281.117,124.498 ; IS3_47pF.2@294.836,116.712 292.632,117.221 ; IS3_47pF.2@294.836,117.73 292.632,117.221 ; IS3_47pF.2@294.952,116.712 297.156,117.221 IS3_47pF.2@294.952,117.73 ; IS9.2@298.005,119.568 298.45,118.11 ; IS9.2@298.42,119.185 300.778,119.253 ; IS9.2@298.565,120.069 300.778,119.253 ; IS9.2@298.895,119.568 298.45,118.11 ; IS_6.1@302.075,118.744 299.871,119.253 ; IS_6.1@302.075,119.762 299.871,119.253 ; IS_6.1@302.133,119.253 299.871,119.253 ; IS_6.1@302.387,119.253 298.831,119.253 IS9.2@298.45,119.634 ; 292.632,117.221 IS3_47pF.2@294.894,117.221 ; IS3_47pF.2@294.894,117.221 297.561,117.221 298.45,118.11 ; 298.45,118.11 IS9.2@298.45,119.634 ; IS9.2@298.45,119.634 300.778,119.253
"NetInductive IC(7407)_6": "Inductive IC(7407).6" LLC_InductiveSensor.P$8 | length 13.8
  Top Layer w0.5: LLC_InductiveSensor.P$8@276.82,121.703 278.384,121.412 ; LLC_InductiveSensor.P$8@276.987,122.174 278.384,121.412 ; LLC_InductiveSensor.P$8@276.987,122.301 277.495,122.301 278.384,121.412 ; LLC_InductiveSensor.P$8@277.292,122.57 278.384,121.412 ; 280.985,120.866 278.751,121.412 280.985,121.958 ; 281.051,121.412 278.384,121.412
NetIS2_1: IS2.1 IS_2.2 | length 16.5
  Top Layer w0.5: IS_2.2@302.768,150.241 306.324,150.241 307.721,151.638 ; IS_2.2@303.022,150.241 305.284,150.241 ; IS_2.2@303.08,149.732 305.284,150.241 ; IS_2.2@303.08,150.75 305.284,150.241 ; IS2.1@307.277,152.963 307.721,151.638 ; IS2.1@307.721,153.035 307.721,151.638 ; IS2.1@308.165,152.963 307.721,151.638
NetIS2_2: IS2.2 IS3.2 IS_1.1 | length 25.8
  Top Layer w0.5: IS2.2@307.273,145.461 307.721,147.615 IS2.2@308.169,145.461 ; IS2.2@307.721,145.415 307.721,148.717 308.229,149.225 310.007,149.225 310.896,150.114 IS3.2@310.896,153.035 313.563,153.035 ; IS3.2@310.448,152.989 310.896,150.835 IS3.2@311.344,152.989 ; IS3.2@310.942,152.587 313.096,153.035 IS3.2@310.942,153.483
NetIS4_1: IS4.1 IS_1.2 | length 15.5
  Top Layer w0.5: IS_1.2@315.214,150.241 316.992,150.241 ; IS_1.2@315.468,150.241 316.992,150.241 ; IS_1.2@315.554,149.736 316.992,150.241 ; IS_1.2@315.554,150.746 316.992,150.241 ; IS4.1@320.222,152.591 318.897,153.035 ; IS4.1@320.222,153.479 318.897,153.035 ; 316.992,150.241 318.262,151.511 318.262,152.4 318.897,153.035 ; 318.897,153.035 IS4.1@320.294,153.035 318.897,153.035
NetIS6_2: IS6.2 IS7.2 IS_3.1 | length 26.5
  Top Layer w0.5: IS6.2@307.721,136.652 IS7.2@310.896,136.652 312.39,136.652 ; IS6.2@307.767,136.204 309.921,136.652 IS6.2@307.767,137.1 ; IS7.2@310.85,136.204 308.696,136.652 IS7.2@310.85,137.1 ; IS7.2@310.964,136.207 312.39,136.652 ; IS7.2@310.964,137.097 312.39,136.652 ; IS_3.1@314.822,135.778 312.653,136.652 ; IS_3.1@314.96,136.271 312.653,136.652 ; IS_3.1@314.988,136.782 312.653,136.652 ; IS_3.1@315.214,136.271 314.833,136.652 312.39,136.652
NetIS7_1: IS7.1 IS_4.2 | length 22.9
  Top Layer w0.5: IS_4.2@303.149,133.731 309.626,133.731 310.896,132.461 IS7.1@310.896,129.032 ; IS_4.2@303.403,133.731 305.665,133.731 ; IS_4.2@303.461,133.222 305.665,133.731 ; IS_4.2@303.461,134.24 305.665,133.731 ; IS7.1@310.448,129.078 310.896,131.232 IS7.1@311.344,129.078
NetIS8_1: IS8.1 IS_3.2 | length 20.4
  Top Layer w0.5: IS_3.2@315.214,133.731 319.405,133.731 320.294,134.62 ; IS_3.2@315.468,133.731 317.73,133.731 ; IS_3.2@315.526,133.222 317.73,133.731 ; IS_3.2@315.526,134.24 317.73,133.731 ; IS8.1@319.847,136.602 320.294,134.62 ; IS8.1@320.741,136.602 320.294,134.62 ; 320.294,134.62 IS8.1@320.294,136.652 320.294,134.62
NetIS10_2: IS10.2 IS11.2 IS_5.1 | length 30.3
  Top Layer w0.5: IS10.2@307.721,119.634 IS11.2@310.896,119.634 ; IS10.2@307.767,119.186 309.921,119.634 IS10.2@307.767,120.082 ; IS11.2@310.85,119.186 308.696,119.634 IS11.2@310.85,120.082 ; IS11.2@310.866,119.185 313.228,119.253 ; IS11.2@311.011,120.069 313.228,119.253 ; IS_5.1@314.902,118.744 312.698,119.253 ; IS_5.1@314.902,119.762 312.698,119.253 ; IS_5.1@314.96,119.253 312.698,119.253 ; IS_5.1@315.214,119.253 311.277,119.253 IS11.2@310.896,119.634 ; IS11.2@310.896,119.634 313.228,119.253
NetIS11_1: IS11.1 IS_6.2 | length 23.2
  Top Layer w0.5: IS_6.2@302.387,116.713 308.864,116.713 310.896,114.681 IS11.1@310.896,112.014 ; IS_6.2@302.641,116.713 304.903,116.713 ; IS_6.2@302.699,116.204 304.903,116.713 ; IS_6.2@302.699,117.222 304.903,116.713 ; IS11.1@310.448,112.06 310.896,114.214 IS11.1@311.344,112.06
NetIS12_1: IS12.1 IS_5.2 | length 16.5
  Top Layer w0.5: IS_5.2@315.214,116.713 318.135,116.713 318.643,117.221 318.643,119.126 319.151,119.634 ; IS_5.2@315.468,116.713 317.73,116.713 ; IS_5.2@315.526,116.204 317.73,116.713 ; IS_5.2@315.526,117.222 317.73,116.713 ; IS12.1@320.205,119.193 319.151,119.634 ; IS12.1@320.205,120.075 319.151,119.634 ; IS12.1@320.294,119.634 319.151,119.634
NetKANAN_5: KANAN.5 KANAN.6
NetKANAN_7: KANAN.7
NetKANAN_8: KANAN.8
NetKANAN_9: KANAN.9
NetKANAN_10: KANAN.10
NetKANAN_11: KANAN.11 LLC_SolenoidValve1.P$5 | length 78.3
  Top Layer w0.3: KANAN.11@263.918,199.544 265.557,200.279 ; KANAN.11@264.065,199.279 265.557,200.279 ; KANAN.11@264.287,199.009 265.557,200.279 ; KANAN.11@264.557,198.787 265.557,200.279 ; KANAN.11@264.822,198.64 265.557,200.279 ; v2@270.462,198.655 269.882,200.272 ; v2@270.736,198.782 269.882,200.272 ; v2@271.035,198.999 269.882,200.272 ; v2@271.239,199.219 269.882,200.272 ; v1@272.521,188.874 274.032,187.994 v1@273.152,189.505 ; v1(272.796,189.23) 276.352,185.674 276.352,172.466 279.4,169.418 LLC_SolenoidValve1.P$5@281.305,169.418 ; LLC_SolenoidValve1.P$5@281.196,168.828 279.655,169.418 ; LLC_SolenoidValve1.P$5@281.196,170.008 279.655,169.418 ; LLC_SolenoidValve1.P$5@281.278,169.119 279.655,169.418 ; LLC_SolenoidValve1.P$5@281.278,169.717 279.655,169.418 ; 265.557,200.279 269.875,200.279 270.891,199.263 v2(270.891,198.882) 269.882,200.272
  Bottom Layer w0.3: v2@270.412,198.805 270.891,197.347 ; v2@270.706,198.871 270.891,197.347 ; v2(270.891,198.882) 270.891,191.135 v1(272.796,189.23) ; v2@271.076,198.871 270.891,197.347 ; v2@271.37,198.805 270.891,197.347 ; v1@272.44,188.955 271.56,190.466 v1@273.071,189.586
NetKANAN_12: KANAN.12
NetKANAN_13: KANAN.13 LLC_SolenoidValve1.P$1 | length 45.2
  Top Layer w0.3: KANAN.13@263.918,197.004 265.557,197.739 ; KANAN.13@264.065,196.739 265.557,197.739 ; KANAN.13@264.287,196.469 265.557,197.739 ; KANAN.13@264.557,196.247 265.557,197.739 ; KANAN.13@264.822,196.1 265.557,197.739 ; LLC_SolenoidValve1.P$1@281.196,178.988 279.655,179.578 ; LLC_SolenoidValve1.P$1@281.196,180.168 279.655,179.578 ; LLC_SolenoidValve1.P$1@281.278,179.279 279.655,179.578 ; LLC_SolenoidValve1.P$1@281.278,179.877 279.655,179.578 ; 265.557,197.739 268.859,197.739 278.13,188.468 278.13,180.467 279.019,179.578 LLC_SolenoidValve1.P$1@281.305,179.578 279.655,179.578
NetKANAN_14: KANAN.14 LLC_SolenoidValve1.P$2 | length 43.8
  Top Layer w0.3: KANAN.14@266.517,195.897 268.465,195.212 ; KANAN.14@266.638,196.174 268.465,195.212 ; KANAN.14@267.063,196.728 268.465,195.212 ; KANAN.14@267.299,196.916 268.465,195.212 ; LLC_SolenoidValve1.P$2@281.196,176.448 279.655,177.038 ; LLC_SolenoidValve1.P$2@281.196,177.628 279.655,177.038 ; LLC_SolenoidValve1.P$2@281.278,176.739 279.655,177.038 ; LLC_SolenoidValve1.P$2@281.278,177.337 279.655,177.038 ; LLC_SolenoidValve1.P$2@281.305,177.038 279.273,177.038 277.241,179.07 277.241,186.436 267.208,196.469 KANAN.14@266.827,196.469 268.465,195.212
NetKANAN_15: KANAN.15
NetKANAN_16: KANAN.16
NetKANAN_17: KANAN.17
NetKANAN_18: KANAN.18
NetKANAN_19: "LLC_CAN bus.P$6" KANAN.19 | length 125.7
  Top Layer w0.3: KANAN.19@263.918,188.314 265.557,187.579 ; KANAN.19@264.065,188.579 265.557,187.579 ; KANAN.19@264.287,188.849 265.557,187.579 ; KANAN.19@264.557,189.071 265.557,187.579 ; KANAN.19@264.822,189.218 265.557,187.579 ; 269.621,187.579 265.557,187.579
  Top Layer w0.5: 269.621,187.579 270.256,186.944 270.256,112.268 282.829,99.695 282.829,90.297 287.147,85.979 ; 288.319,85.489 287.147,85.979 ; 288.319,86.469 287.147,85.979 ; 288.417,85.979 287.147,85.979
NetKANAN_20: "LLC_CAN bus.P$5" KANAN.20 | length 120.7
  Top Layer w0.5: KANAN.20@266.827,188.849 270.637,188.849 271.526,187.96 271.526,113.411 284.099,100.838 284.099,97.663 285.623,96.139 285.623,90.043 287.147,88.519 ; KANAN.20@266.893,188.303 269.127,188.849 KANAN.20@266.893,189.395 ; 288.319,88.029 287.147,88.519 ; 288.319,89.009 287.147,88.519 ; 287.147,88.519 288.417,88.519 287.147,88.519
NetKANAN_21: KANAN.21
NetKANAN_22: KANAN.22
NetKANAN_23: "LLC_CAN bus.P$1" KANAN.23 | length 120.1
  Top Layer w0.5: v1@273.403,182.058 274.447,181.737 ; v1@273.804,182.621 274.447,181.737 ; 287.92,98.735 288.417,100.929 288.914,98.735 ; 288.417,98.679 288.417,101.727 273.939,116.205 273.939,138.684 274.447,139.192 274.447,181.737 ; 274.447,181.737 v1(273.558,182.372) 273.558,182.626 274.447,181.737
  Bottom Layer w0.3: KANAN.23@263.92,183.233 265.537,182.519 ; KANAN.23@264.065,183.498 265.537,182.519 ; KANAN.23@264.287,183.769 265.537,182.519 ; KANAN.23@264.558,183.991 265.537,182.519 ; KANAN.23@264.823,184.136 265.537,182.519 ; v1@273.449,181.935 272.038,182.519 ; v1@273.535,182.821 272.038,182.519 ; 265.537,182.519 273.411,182.519 v1(273.558,182.372) 272.038,182.519
NetKANAN_24: KANAN.24
NetKANAN_25: KANAN.25
NetKANAN_26: "LLC_CAN bus.P$2" KANAN.26 | length 126.3
  Top Layer w0.5: v1@272.447,179.809 272.757,177.731 ; v1@273.144,179.796 272.757,177.731 ; 288.12,95.737 286.202,97.465 ; 288.631,96.591 286.202,97.465 ; 272.757,177.731 v1(272.796,179.832) 272.757,179.793 272.757,114.593 285.623,101.727 285.623,98.044 287.528,96.139 ; 286.202,97.465 288.417,96.139 ; 287.528,96.139 288.417,96.139 ; 287.528,96.139 288.276,96.619 287.528,96.139 ; 287.528,96.139 288.276,95.659 287.528,96.139 ; 287.528,96.139 288.417,96.139 ; 287.528,96.139 288.417,96.139
  Bottom Layer w0.3: KANAN.26@266.827,181.229 268.097,181.229 ; KANAN.26@266.875,180.882 268.097,181.229 ; KANAN.26@266.875,181.576 268.097,181.229 ; KANAN.26@266.993,180.601 268.097,181.229 ; KANAN.26@266.993,181.857 268.097,181.229 ; v1@272.692,179.394 271.285,179.959 ; v1@272.767,180.281 271.285,179.959 ; 268.097,181.229 269.367,179.959 272.669,179.959 v1(272.796,179.832) 271.285,179.959
NetKANAN_27: KANAN.27
NetKANAN_28: KANAN.28
NetKANAN_29: KANAN.29
NetKANAN_30: KANAN.30
NetKANAN_31: KANAN.31 LLC_1.P$1 | length 169.7
  Top Layer w0.3: v1@218.64,240.17 219.075,239.395 ; v1@219.51,240.17 219.075,239.395 ; v1@248.608,229.587 247.116,230.505 ; v1@248.867,230.441 247.116,230.505 ; v1@257.746,215.451 258.191,214.019 ; v1@258.636,215.451 258.191,214.019 ; KANAN.31@264.079,172.993 263.271,173.609 ; KANAN.31@264.079,174.225 263.271,173.609 ; KANAN.31@264.227,173.264 263.271,173.609 ; KANAN.31@264.227,173.954 263.271,173.609 ; KANAN.31@264.287,173.609 263.271,173.609 ; 219.075,239.395 v1(219.075,240.284) 219.075,239.395 ; 219.075,239.395 227.965,230.505 248.285,230.505 v1(248.793,229.997) 247.116,230.505 ; 258.191,214.019 v1(258.191,215.519) 258.191,178.689 263.271,173.609
  Bottom Layer w0.3: LLC_1.P$1@183.769,236.093 185.42,236.093 188.341,239.014 203.2,239.014 204.47,240.284 v1(219.075,240.284) ; LLC_1.P$1@183.796,235.794 185.419,236.093 ; LLC_1.P$1@183.796,236.392 185.419,236.093 ; LLC_1.P$1@183.878,235.503 185.419,236.093 ; LLC_1.P$1@183.878,236.683 185.419,236.093 ; v1@219.007,239.839 217.575,240.284 v1@219.007,240.729 ; v1@248.585,229.598 250.299,228.958 ; v1(248.793,229.997) 250.299,228.958 ; v1@248.955,230.089 249.169,230.089 258.191,221.067 v1(258.191,215.519) ; v1@249.092,230.333 250.299,228.958 ; v1@257.746,215.587 258.191,217.019 v1@258.636,215.587
NetKANAN_32: KANAN.32
NetKANAN_33: KANAN.33 LLC_1.P$5 | length 177.8
  Top Layer w0.3: LLC_1.P$5@183.592,245.68 182.753,246.253 ; LLC_1.P$5@183.592,246.826 182.753,246.253 ; LLC_1.P$5@183.725,245.956 182.753,246.253 ; LLC_1.P$5@183.725,246.55 182.753,246.253 ; LLC_1.P$5@183.769,246.253 182.753,246.253 ; v1@248.598,227.393 247.166,227.838 ; v1@248.598,228.283 247.166,227.838 ; v1(248.666,227.838) 247.166,227.838 ; v1@248.92,227.838 226.949,227.838 215.773,239.014 215.773,246.507 210.439,251.841 183.769,251.841 182.245,250.317 182.245,246.761 182.753,246.253 ; v1@256.476,213.673 256.921,212.241 ; v1@257.175,213.487 v1(256.921,213.741) ; v1@257.366,213.673 256.921,212.241 ; KANAN.33@264.102,170.446 263.144,171.069 ; KANAN.33@264.102,171.692 263.144,171.069 ; KANAN.33@264.233,170.723 263.144,171.069 ; KANAN.33@264.233,171.415 263.144,171.069 ; KANAN.33@264.287,171.069 263.144,171.069 ; 256.921,212.241 v1(256.921,213.741) ; v1(256.921,213.741) 256.921,178.054 262.128,172.847 262.128,172.085 263.144,171.069
  Bottom Layer w0.3: v1@248.446,227.445 250.117,226.768 ; v1@248.976,228.164 250.117,226.768 ; v1@256.476,213.809 256.921,215.241 v1@257.366,213.809 ; v1@257.175,213.487 v1(256.921,213.741) 256.921,219.964 249.047,227.838 v1(248.666,227.838) 250.117,226.768
NetKANAN_34: KANAN.34 LLC_1.P$2 | length 181.1
  Top Layer w0.3: v1@216.852,241.994 217.297,240.562 v1@217.742,241.994 ; v1(217.297,242.062) 217.297,239.395 227.711,228.981 v1(246.38,228.981) 244.88,228.981 ; v1@246.312,228.536 244.88,228.981 ; v1@246.312,229.426 244.88,228.981 ; v1@255.333,211.895 255.778,210.463 ; v1@256.223,211.895 255.778,210.463 ; KANAN.34@266.292,171.438 265.557,169.799 ; KANAN.34@266.557,171.291 265.557,169.799 ; KANAN.34@267.049,170.799 265.557,169.799 ; KANAN.34@267.196,170.534 265.557,169.799 ; 255.778,210.463 v1(255.778,211.963) 255.778,177.419 261.112,172.085 261.112,170.815 262.128,169.799 265.557,169.799 ; 265.557,169.799 KANAN.34@266.827,171.069 265.557,169.799
  Bottom Layer w0.3: LLC_1.P$2@183.769,238.633 186.309,238.633 187.579,239.903 201.676,239.903 203.835,242.062 v1(217.297,242.062) ; LLC_1.P$2@183.796,238.334 185.419,238.633 ; LLC_1.P$2@183.796,238.932 185.419,238.633 ; LLC_1.P$2@183.878,238.043 185.419,238.633 ; LLC_1.P$2@183.878,239.223 185.419,238.633 ; v1@217.229,241.617 215.797,242.062 v1@217.229,242.507 ; v1@246.04,228.687 247.424,227.429 ; v1@246.781,229.185 247.424,227.429 ; v1@255.333,212.031 255.778,213.463 v1@256.223,212.031 ; v1(255.778,211.963) 255.778,219.075 246.38,228.473 v1(246.38,228.981) 247.424,227.429
NetKANAN_35: KANAN.35
NetKANAN_36: KANAN.36 LLC_1.P$6 | length 183.4
  Top Layer w0.3: LLC_1.P$6@183.415,249.277 185.155,250.179 ; LLC_1.P$6@183.574,249.021 185.155,250.179 ; LLC_1.P$6@183.769,248.793 185.547,250.571 210.185,250.571 214.503,246.253 214.503,238.506 226.695,226.314 v1@246.062,226.314 ; LLC_1.P$6@183.997,248.598 185.155,250.179 ; LLC_1.P$6@184.253,248.439 185.155,250.179 ; v1@246.312,225.869 244.88,226.314 ; v1@246.312,226.759 244.88,226.314 ; v1(246.38,226.314) 244.88,226.314 ; v1@254.19,210.117 254.635,208.685 ; v1(254.635,210.185) 254.635,208.685 ; v1@254.635,210.693 254.635,176.403 259.144,171.894 259.144,168.593 260.497,167.239 265.537,167.239 ; v1@255.08,210.117 254.635,208.685 ; KANAN.36@266.293,168.899 265.537,167.239 ; KANAN.36@266.557,168.752 265.537,167.239 ; KANAN.36@267.05,168.259 265.537,167.239 ; KANAN.36@267.197,167.995 265.537,167.239 ; 265.537,167.239 KANAN.36@266.827,168.529 265.537,167.239
  Bottom Layer w0.3: v1@246.105,225.958 247.616,225.078 v1@246.736,226.589 ; v1(246.38,226.314) 254.635,218.059 v1@254.635,210.693 ; v1@254.19,210.253 254.635,211.685 ; v1(254.635,210.185) 254.635,211.685 ; v1@255.08,210.253 254.635,211.685
NetKANAN_37: KANAN.37
NetKANAN_38: KANAN.38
